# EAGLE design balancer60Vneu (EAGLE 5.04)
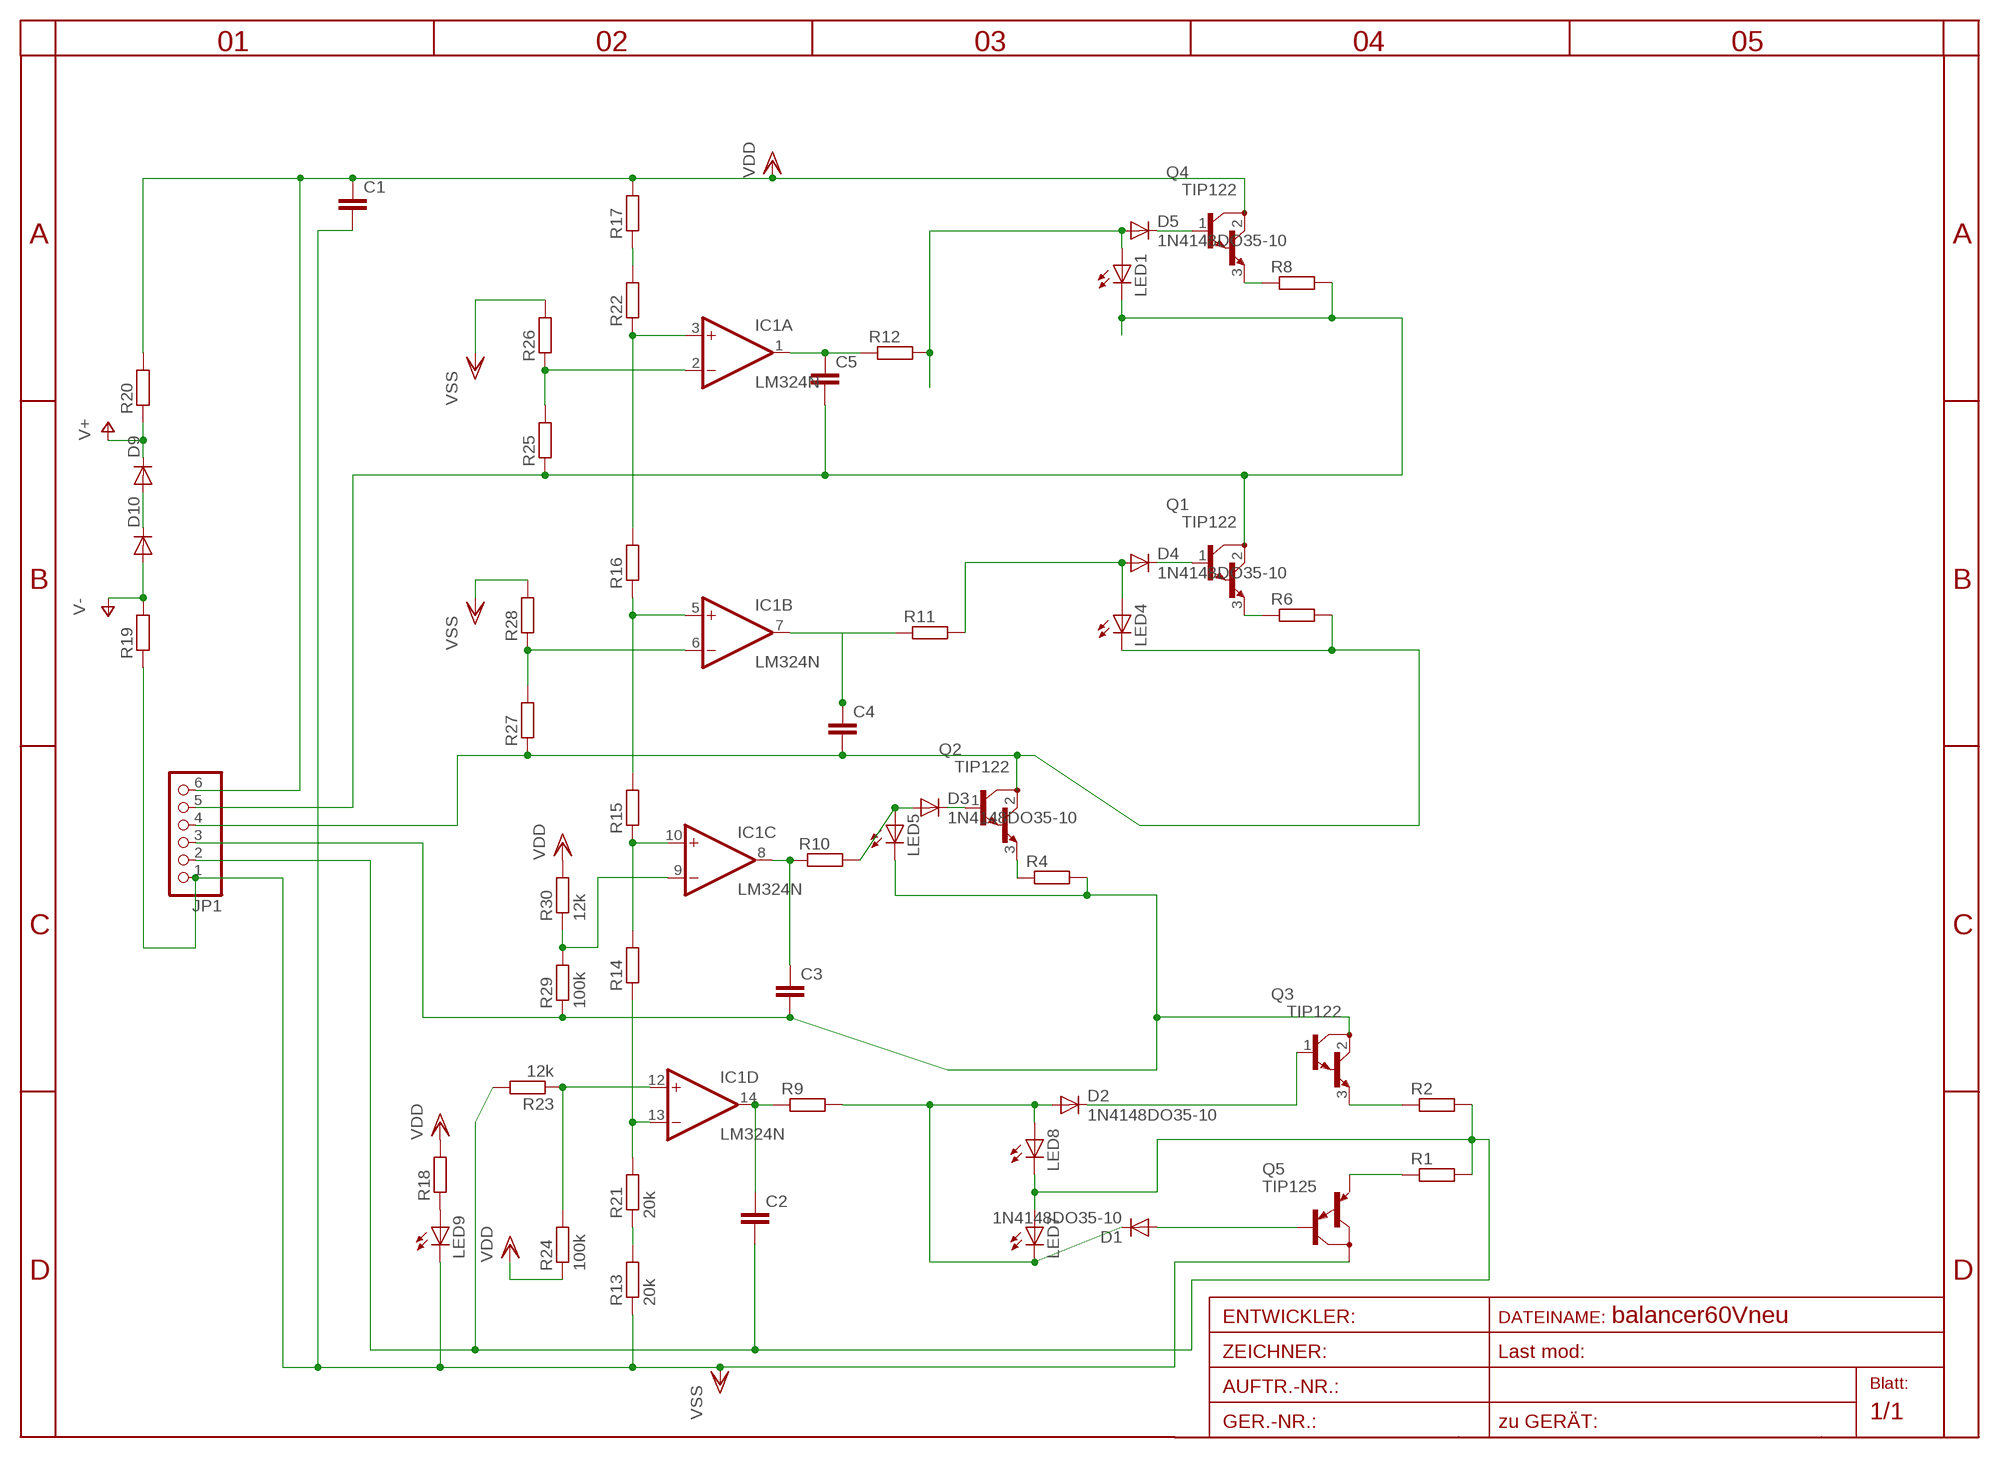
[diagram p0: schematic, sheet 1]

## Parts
C1  C-EU025-024X044  [C025-024X044]
C2  C-EU025-024X044  [C025-024X044]
C3  C-EU025-024X044  [C025-024X044]
C4  C-EU025-024X044  [C025-024X044]
C5  C-EU025-024X044  [C025-024X044]
D1  1N4148DO35-10  [DO35-10]
D2  1N4148DO35-10  [DO35-10]
D3  1N4148DO35-10  [DO35-10]
D4  1N4148DO35-10  [DO35-10]
D5  1N4148DO35-10  [DO35-10]
D9  DIODE-D-10  [D-10]
D10  DIODE-D-10  [D-10]
IC1  LM324N  [DIL14]
JP1  PINHD-1X6  [1X06]
LED1  LED3MM  [LED3MM]
LED4  LED3MM  [LED3MM]
LED5  LED3MM  [LED3MM]
LED7  LED3MM  [LED3MM]
LED8  LED3MM  [LED3MM]
LED9  LED3MM  [LED3MM]
Q1  TIP122  [TO220]
Q2  TIP122  [TO220]
Q3  TIP122  [TO220]
Q4  TIP122  [TO220]
Q5  TIP125  [TO220]
R1  R-EU_0207/10  [0207/10]
R2  R-EU_0207/10  [0207/10]
R4  R-EU_0207/10  [0207/10]
R6  R-EU_0207/10  [0207/10]
R8  R-EU_0207/10  [0207/10]
R9  R-EU_0207/10  [0207/10]
R10  R-EU_0207/10  [0207/10]
R11  R-EU_0204/5  [0204/5]
R12  R-EU_0207/10  [0207/10]
R13  20k  R-EU_0204/5  [0204/5]
R14  R-EU_0204/5  [0204/5]
R15  R-EU_0204/5  [0204/5]
R16  R-EU_0204/5  [0204/5]
R17  R-EU_0204/5  [0204/5]
R18  R-EU_0204/5  [0204/5]
R19  R-EU_0204/5  [0204/5]
R20  R-EU_0204/5  [0204/5]
R21  20k  R-EU_0204/5  [0204/5]
R22  R-EU_0204/5  [0204/5]
R23  12k  R-EU_0204/5  [0204/5]
R24  100k  R-EU_0204/5  [0204/5]
R25  R-EU_0204/5  [0204/5]
R26  R-EU_0204/5  [0204/5]
R27  R-EU_0204/5  [0204/5]
R28  R-EU_0204/5  [0204/5]
R29  100k  R-EU_0204/5  [0204/5]
R30  12k  R-EU_0204/5  [0204/5]

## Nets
N$1: D1.C D2.A LED7.K(C) LED8.A R9.2
N$2: C2.2 JP1.2 LED7.A LED8.K(C) R1.2 R2.2 R23.2
N$3: D3.C Q2.1(B)
N$4: D4.C Q1.1(B)
N$5: D5.C Q4.1(B)
N$6: C3.2 JP1.3 LED5.K(C) Q3.2(C) R4.2 R29.1
N$7: C5.2 JP1.5 LED1.K(C) Q1.2(C) R8.2 R25.1
N$9: D2.C Q3.1(B)
N$10: D3.A LED5.A R10.2
N$11: D4.A LED4.A R11.2
N$12: D5.A LED1.A R12.2
N$13: Q3.3(E) R2.1
N$15: Q1.3(E) R6.1
N$17: Q2.3(E) R4.1
N$18: Q4.3(E) R8.1
N$20: C5.1 IC1.1(A:OUT) R12.1
N$21: C4.1 IC1.7(B:OUT) R11.1
N$23: R17.1 R22.2
N$24: C3.1 IC1.8(C:OUT) R10.1
N$25: C2.1 IC1.14(D:OUT) R9.1
N$26: IC1.10(C:+IN) R14.2 R15.1
N$28: IC1.13(D:-IN) R14.1 R21.2
N$29: R13.2 R21.1
N$32: IC1.3(A:+IN) R16.2 R22.1
N$34: LED9.A R18.1
N$35: D9.A D10.C
N$36: IC1.5(B:+IN) R15.2 R16.1
N$37: IC1.12(D:+IN) R23.1 R24.2
N$38: C4.2 JP1.4 LED4.K(C) Q2.2(C) R6.2 R27.1
N$40: IC1.2(A:-IN) R25.2 R26.1
N$41: IC1.6(B:-IN) R27.2 R28.1
N$42: IC1.9(C:-IN) R29.2 R30.1
N$43: Q5.3(E) R1.1
N$44: D1.A Q5.1(B)
V+: D9.C R20.1
V-: D10.A R19.2
VDD: C1.1 JP1.6 Q4.2(C) R17.2 R18.2 R20.2 R24.1 R30.2
VSS: C1.2 JP1.1 LED9.K(C) Q5.2(C) R13.1 R19.1 R26.2 R28.2

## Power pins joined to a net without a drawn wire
V+: IC1.4(P:V+)
V-: IC1.11(P:V-)

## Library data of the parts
C1-C5 = rcl-2:C-EU: CAPACITOR, European symbol
D1-D5 = diode-1:1N4148: DIODE
D9 D10 = diode-1:DIODE-: DIODE
IC1 = linear:LM324: OP AMP
JP1 = pinhead:PINHD-1X6: PIN HEADER
LED1 LED4 LED5 LED7-LED9 = led:LED: LED
Q1-Q4 = transistor-npn:TIP122*: NPN Darlington Transistor
Q5 = transistor-pnp:TIP125: PNP Transistor
R1 R2 R4 R6 R8-R30 = rcl-2:R-EU_: RESISTOR, European symbol

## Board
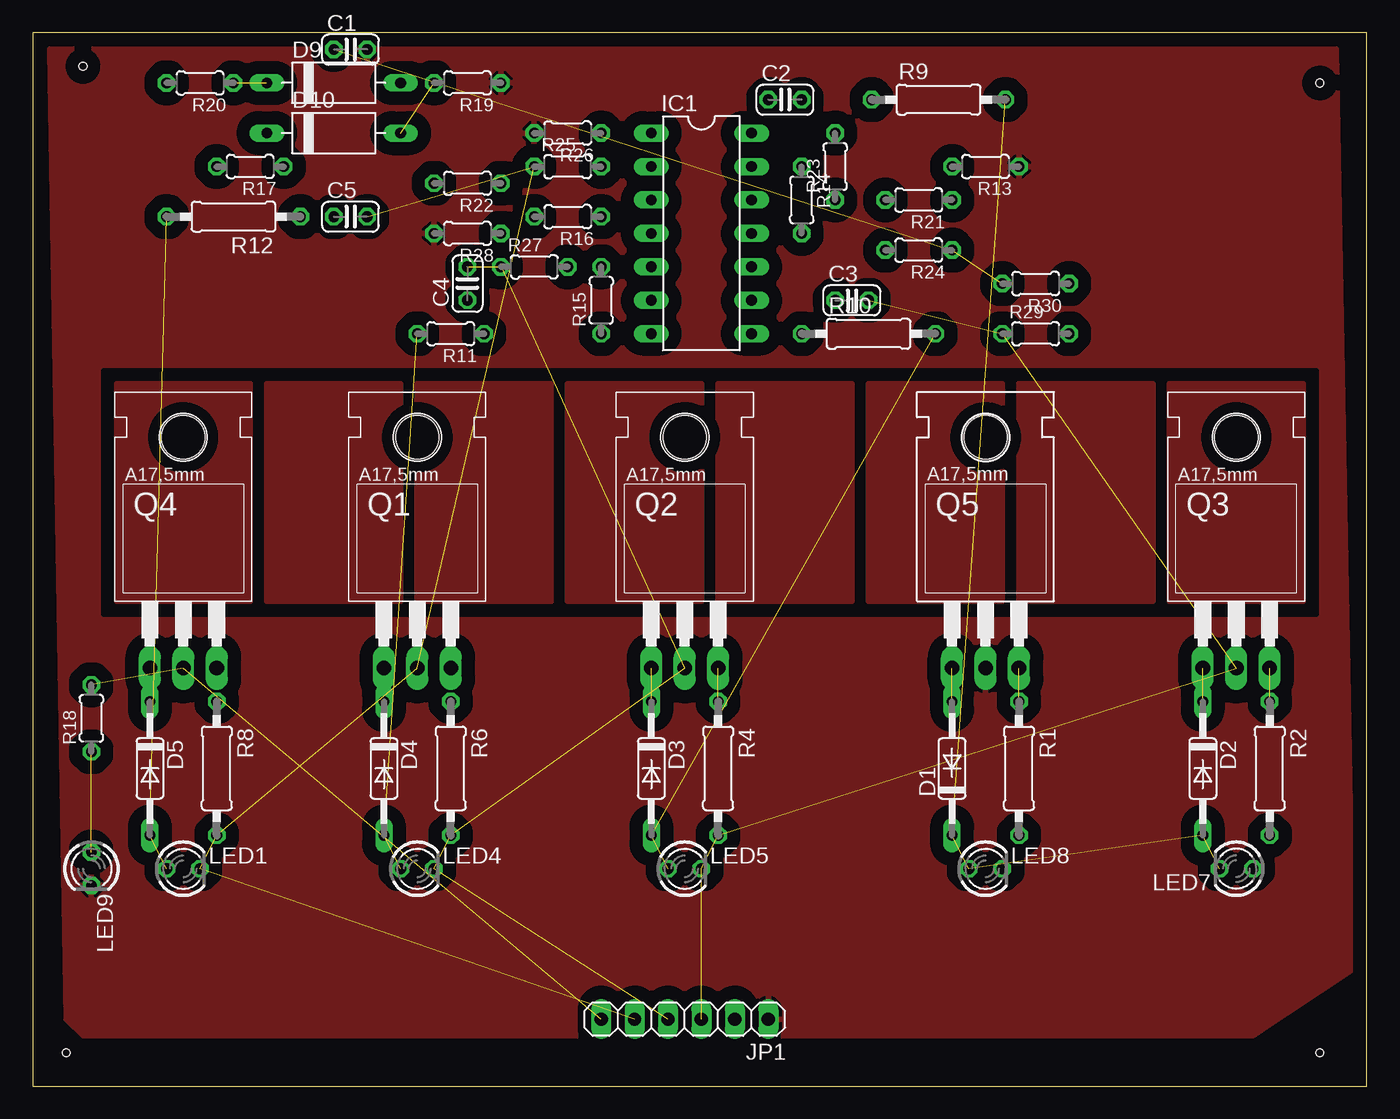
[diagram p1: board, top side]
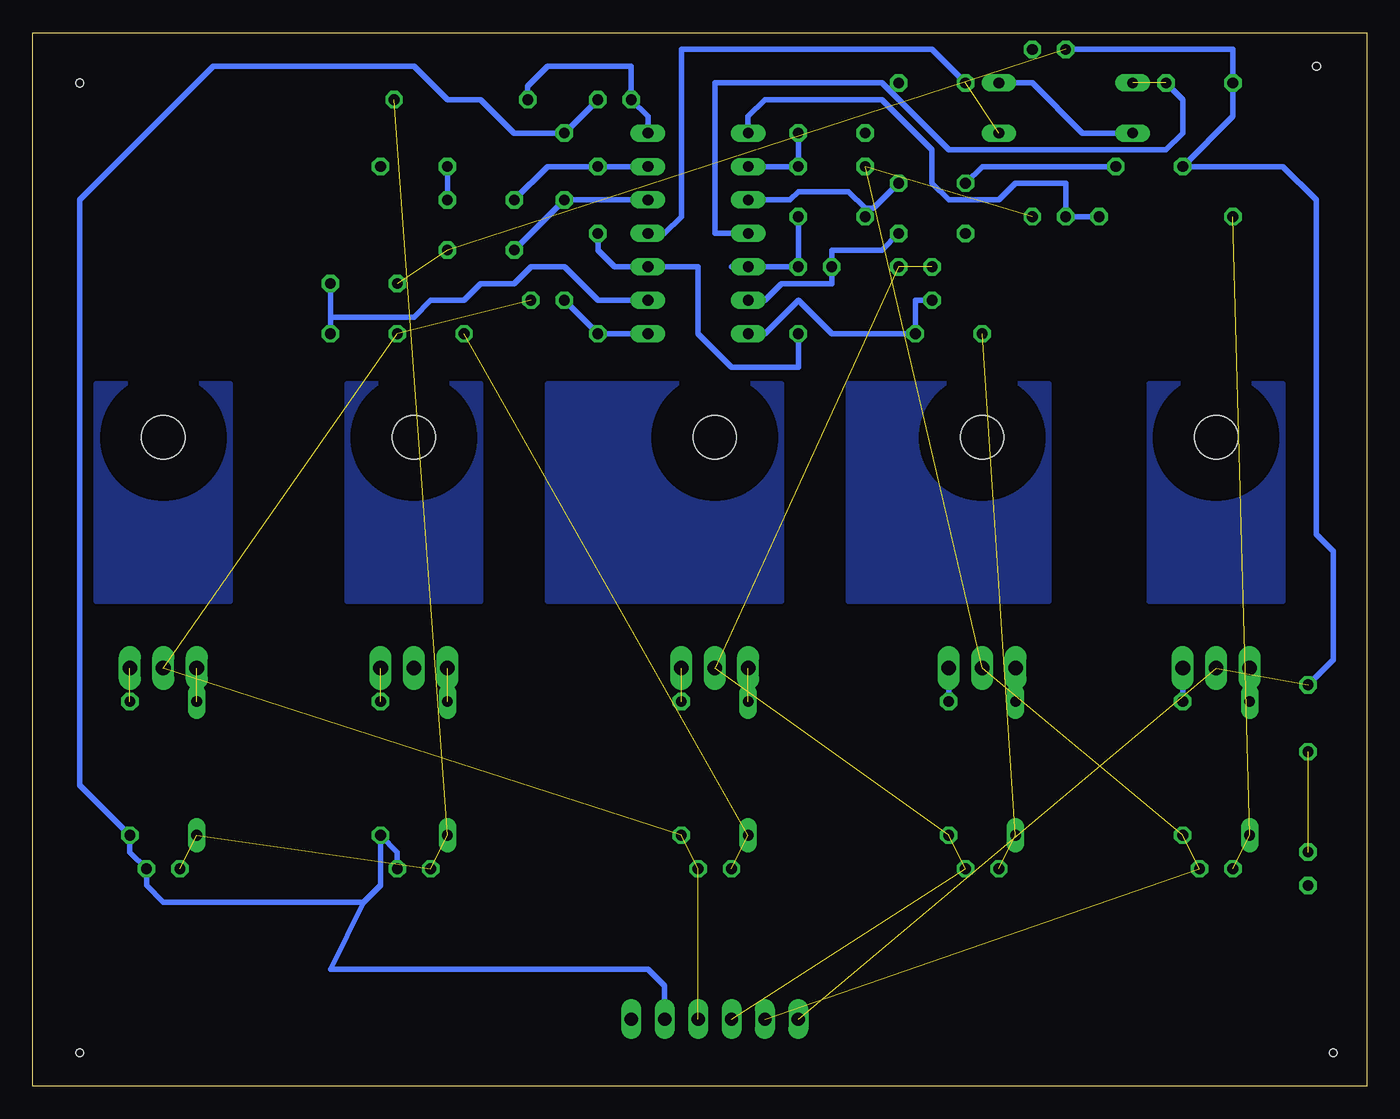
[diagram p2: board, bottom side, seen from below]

Size 101.35 x 80 mm. Coordinates in mm from the lower left corner, seen from the top.
Outline: 0,0 101.35,0 101.35,80 0,80 0,0
Copper layers (1*16): Top 0.035mm / dielectric 1.5mm / Bottom 0.035mm
Design rules "default": minimum track width 10mil, minimum drill 24mil, track to track 8mil, track to pad 8mil, pad to pad 8mil, via to via 8mil, smd to smd 8mil, copper to edge 40mil, drill to drill 8mil, minimum pad ring 10mil, minimum via ring 8mil, stop-mask expansion 4mil, vias tented up to drill 0mil, thermal gap 10mil
Holes 0.6 mm at 2.54,2.54 97.79,2.54 97.79,76.2 3.81,77.47

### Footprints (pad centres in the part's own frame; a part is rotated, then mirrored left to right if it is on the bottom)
C025-024X044 = drill 0.813 octagon: 1 -1.27,0; 2 1.27,0
DO35-10 = drill 0.813 long: A 5.08,0; C -5.08,0
D-10 = drill 0.813 long: A 5.08,0; C -5.08,0
DIL14 = drill 0.813 long: 1 -7.62,-3.81; 2 -5.08,-3.81; 3 -2.54,-3.81; 4 0,-3.81; 5 2.54,-3.81; 6 5.08,-3.81; 7 7.62,-3.81; 8 7.62,3.81; 9 5.08,3.81; 10 2.54,3.81; 11 0,3.81; 12 -2.54,3.81; 13 -5.08,3.81; 14 -7.62,3.81
1X06 = drill 1.016 long: 1 -6.35,0; 2 -3.81,0; 3 -1.27,0; 4 1.27,0; 5 3.81,0; 6 6.35,0
LED3MM = drill 0.813 octagon: A -1.27,0; K 1.27,0
TO220 = drill 1.118 long: 1 -2.54,-6.35; 2 0,-6.35; 3 2.54,-6.35 | hole 3.302: 0,11.176
0207/10 = drill 0.813 octagon: 1 -5.08,0; 2 5.08,0
0204/5 = drill 0.813 octagon: 1 -2.54,0; 2 2.54,0

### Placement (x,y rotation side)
C1  24.13,78.74 0 top
C2  57.15,74.93 0 top
C3  62.23,59.69 0 top
C4  33.02,60.96 90 top
C5  24.13,66.04 0 top
D1  69.85,24.13 90 top
D2  88.9,24.13 270 top
D3  46.99,24.13 270 top
D4  26.67,24.13 270 top
D5  8.89,24.13 270 top
D9  22.86,76.2 0 top
D10  22.86,72.39 0 top
IC1  50.8,64.77 270 top
JP1  49.53,5.08 180 top
LED1  11.43,16.51 0 top
LED4  29.21,16.51 0 top
LED5  49.53,16.51 0 top
LED7  91.44,16.51 180 top
LED8  72.39,16.51 0 top
LED9  4.45,16.51 270 top
Q1  29.21,38.1 0 top
Q2  49.53,38.1 0 top
Q3  91.44,38.1 0 top
Q4  11.43,38.1 0 top
Q5  72.39,38.1 0 top
R1  74.93,24.13 270 top
R2  93.98,24.13 270 top
R4  52.07,24.13 270 top
R6  31.75,24.13 270 top
R8  13.97,24.13 270 top
R9  68.82,74.93 0 top
R10  63.5,57.15 0 top
R11  31.75,57.15 180 top
R12  15.24,66.04 180 top
R13  72.39,69.85 180 top
R14  58.42,67.31 270 top
R15  43.18,59.69 90 top
R16  40.64,66.04 180 top
R17  16.51,69.85 180 top
R18  4.45,27.94 90 top
R19  33.02,76.2 180 top
R20  12.7,76.2 180 top
R21  67.31,67.31 180 top
R22  33.02,68.58 180 top
R23  60.96,69.85 90 top
R24  67.31,63.5 180 top
R25  40.64,69.85 0 top
R26  40.64,72.39 180 top
R27  38.1,62.23 0 top
R28  33.02,64.77 180 top
R29  76.2,57.15 0 top
R30  76.2,60.96 180 top

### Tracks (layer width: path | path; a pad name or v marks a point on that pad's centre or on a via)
N$1  (4 unrouted)
N$2
  Bottom 0.406: 76.2,13.97 91.44,13.97 92.71,15.24 LED7.A 93.98,17.78 R2.2 97.79,22.86 97.79,67.31 87.63,77.47 72.39,77.47 69.85,74.93 67.31,74.93 64.77,72.39 R23.2 C2.2 | 76.2,13.97 74.93,15.24 R1.2 73.66,17.78 LED8.K | JP1.2 53.34,7.62 54.61,8.89 78.74,8.89 76.2,13.97
N$3  (1 unrouted)
N$4
  Bottom 0.406: D4.C Q1.1
N$5
  Bottom 0.406: D5.C Q4.1
N$6  (5 unrouted)
N$7  (5 unrouted)
N$9  (1 unrouted)
N$10  (2 unrouted)
N$11  (2 unrouted)
N$12  (2 unrouted)
N$13  (1 unrouted)
N$15
  Bottom 0.406: R6.1 Q1.3
N$17  (1 unrouted)
N$18
  Bottom 0.406: R8.1 Q4.3
N$20
  Bottom 0.406: R12.1 C5.1 22.86,68.58 26.67,68.58 27.94,67.31 31.75,67.31 33.02,68.58 33.02,71.12 36.83,74.93 45.72,74.93 46.99,73.66 IC1.1
N$21
  Bottom 0.406: IC1.7 45.72,57.15 43.18,59.69 40.64,57.15 R11.1 34.29,59.69 C4.1
N$23
  Bottom 0.406: R22.2 29.21,69.85 R17.1
N$24
  Bottom 0.406: IC1.8 R10.1 C3.1
N$25
  Bottom 0.406: R9.1 63.74,75.96 62.23,77.47 55.88,77.47 C2.1 54.61,73.66 IC1.14
N$26
  Bottom 0.406: R14.2 58.42,63.5 57.15,62.23 IC1.10 50.8,62.23 50.8,57.15 48.26,54.61 43.18,54.61 R15.1
N$28
  Bottom 0.406: R21.2 62.23,69.85 R14.1 IC1.13
N$29
  Bottom 0.406: R21.1 R13.2
N$31
  pour Top (isolate 0.61, rank 4): 6.35,53.34 16.51,53.34 16.51,36.83 6.35,36.83
  pour Top (isolate 0.61, rank 4): 17.78,53.34 27.94,53.34 27.94,36.83 17.78,36.83
  pour Top (isolate 0.61, rank 4): 29.21,53.34 39.37,53.34 39.37,36.83 29.21,36.83
  pour Top (isolate 0.61, rank 4): 40.64,53.34 50.8,53.34 50.8,36.83 40.64,36.83
  pour Top (isolate 0.61, rank 4): 52.07,53.34 62.23,53.34 62.23,36.83 52.07,36.83
  pour Top (isolate 0.61, rank 4): 63.5,53.34 73.66,53.34 73.66,36.83 63.5,36.83
  pour Top (isolate 0.61, rank 4): 74.93,53.34 85.09,53.34 85.09,36.83 74.93,36.83
  pour Top (isolate 0.61, rank 4): 86.36,53.34 96.52,53.34 96.52,36.83 86.36,36.83
  pour Bottom (isolate 0.61, rank 4): 6.35,53.34 16.51,53.34 16.51,36.83 6.35,36.83
  pour Bottom (isolate 0.61, rank 4): 29.21,53.34 39.37,53.34 39.37,36.83 29.21,36.83
  pour Bottom (isolate 0.61, rank 4): 24.13,53.34 34.29,53.34 34.29,36.83 24.13,36.83
  pour Bottom (isolate 0.61, rank 4): 52.07,53.34 62.23,53.34 62.23,36.83 52.07,36.83
  pour Bottom (isolate 0.61, rank 4): 44.45,53.34 54.61,53.34 54.61,36.83 44.45,36.83
  pour Bottom (isolate 0.61, rank 4): 67.31,53.34 77.47,53.34 77.47,36.83 67.31,36.83
  pour Bottom (isolate 0.61, rank 4): 86.36,53.34 96.52,53.34 96.52,36.83 86.36,36.83
N$32
  Bottom 0.406: IC1.3 43.81,67.31 43.18,67.94 39.37,67.94 38.1,66.67 | 38.1,66.67 R16.2 | 38.1,66.67 37.47,66.67 R22.1
N$34  (1 unrouted)
N$35
  Bottom 0.406: D10.C 21.59,72.39 25.4,76.2 D9.A
N$36
  Bottom 0.406: R16.1 R15.2 IC1.5 48.26,62.23
N$37
  Bottom 0.406: IC1.12 R23.1 R24.2
N$38  (5 unrouted)
N$40
  Bottom 0.406: IC1.2 R25.2 R26.1
N$41
  Bottom 0.406: IC1.6 45.72,59.69 44.45,60.96 40.64,60.96 R27.2 40.64,63.5 36.83,63.5 R28.1
N$42
  Bottom 0.406: 78.74,58.42 R29.2 | 78.74,58.42 R30.1 | IC1.9 58.42,59.69 60.96,62.23 63.5,62.23 64.77,60.96 67.31,60.96 68.58,59.69 71.12,59.69 72.39,58.42 78.74,58.42
N$43  (1 unrouted)
N$44  (1 unrouted)
V+  (1 unrouted)
  Bottom 0.406: IC1.4 49.53,64.77 49.53,76.2 36.83,76.2 31.75,71.12 15.24,71.12 13.97,72.39 13.97,74.93 R20.1
V-  (1 unrouted)
  Bottom 0.406: IC1.11 53.34,64.77 52.07,66.04 52.07,78.74 33.02,78.74 R19.2
VDD  (4 unrouted)
  Bottom 0.406: C1.1 10.16,78.74 R20.2 10.16,73.66 R17.2 6.35,69.85 3.81,67.31 3.81,41.91 2.54,40.64 2.54,32.38 R18.2
VSS
  pour Top (isolate 1.016, rank 5): 1.27,78.74 99.06,78.74 100.33,8.89 92.71,3.81 3.81,3.81 2.54,5.08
